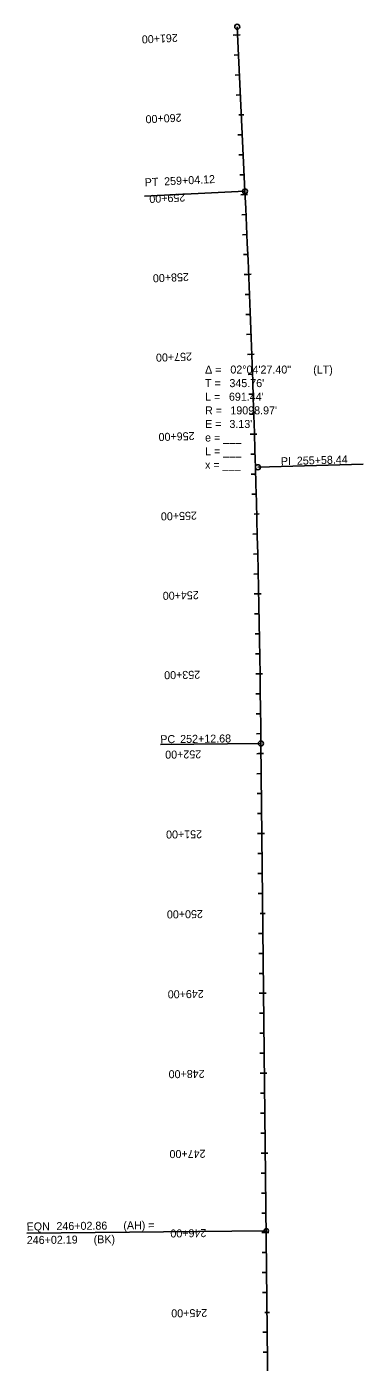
# Model space of a CAD drawing. Extents: x 23417911 to 23421158, y 6737892 to 6791804.
# Drawn here: x 23417967 to 23418389, y 6750912 to 6752584 of the extents above; entities that cross this region are included whole.
import ezdxf

# ---------------------------------------------------------------- set-up
doc = ezdxf.new("R2010")
doc.units = 0
for name, color, linetype in [('Alignment', 7, 'Continuous'), ('TextAlignment', 7, 'Continuous'), ('TextAlignmentLrg', 7, 'Continuous'), ('TextAlignmentSml', 7, 'Continuous')]:
    doc.layers.add(name, color=color, linetype=linetype)

msp = doc.modelspace()

# ---------------------------------------------------------------- linework, layer by layer
at = {"layer": 'Alignment'}
for p, q in [((23418240.7, 6752377.7), (23418231, 6752583.7)), ((23418240.7, 6752377.7), (23418231, 6752583.7)), ((23418292.6, 6748745.2), (23418260.7, 6751686.6)), ((23418292.6, 6748745.2), (23418260.7, 6751686.6))]:
    msp.add_line(p, q, dxfattribs=at)
msp.add_arc((23399162.8, 6751479.5), 19099, 0.62113, 2.69541, dxfattribs=at)
msp.add_arc((23399162.8, 6751479.5), 19099, 0.62113, 2.69541, dxfattribs=at)
at = {"layer": 'TextAlignment'}
for p, q in [((23418240.7, 6752377.7), (23418114.8, 6752371.8)), ((23418114.8, 6752371.8), (23418114.8, 6752371.8)), ((23418256.9, 6752032.3), (23418388.9, 6752036.1)), ((23418388.9, 6752036.1), (23418388.9, 6752036.1)), ((23418260.7, 6751686.6), (23418134.7, 6751685.2)), ((23418134.7, 6751685.2), (23418134.7, 6751685.2)), ((23418267.3, 6751076.8), (23417967.3, 6751073.5))]:
    msp.add_line(p, q, dxfattribs=at)
for centre, radius in [((23418231, 6752583.7), 3.12), ((23418240.7, 6752377.7), 3.12), ((23418256.9, 6752032.3), 3.12), ((23418260.7, 6751686.6), 3.12), ((23418267.3, 6751076.8), 2.67)]:
    msp.add_circle(centre, radius, dxfattribs=at)
at = {"layer": 'TextAlignmentLrg'}
for p, q in [((23418231.5, 6752573.4), (23418226, 6752573.1)), ((23418233.1, 6752473.3), (23418239.2, 6752473.6)), ((23418240.9, 6752373.6), (23418235.4, 6752373.3)), ((23418245.3, 6752273.7), (23418239.8, 6752273.4)), ((23418249.2, 6752173.7), (23418243.7, 6752173.6)), ((23418252.6, 6752073.8), (23418247.1, 6752073.6)), ((23418252.4, 6751973.8), (23418258.5, 6751973.9)), ((23418257.7, 6751873.9), (23418252.3, 6751873.8)), ((23418259.5, 6751773.9), (23418254.1, 6751773.8)), ((23418260.8, 6751673.9), (23418255.4, 6751673.8)), ((23418261.9, 6751573.9), (23418256.5, 6751573.8)), ((23418259.9, 6751473.9), (23418266.1, 6751473.9)), ((23418264.1, 6751373.9), (23418258.6, 6751373.9)), ((23418265.2, 6751273.9), (23418259.7, 6751273.9)), ((23418266.3, 6751173.9), (23418260.8, 6751173.9)), ((23418267.3, 6751074.6), (23418261.9, 6751074.5)), ((23418265.4, 6750974.6), (23418271.5, 6750974.6))]:
    msp.add_line(p, q, dxfattribs=at)
at = {"layer": 'TextAlignmentSml'}
for p, q in [((23418228.4, 6752573.2), (23418234.5, 6752573.5)), ((23418232.6, 6752548.4), (23418227.2, 6752548.1)), ((23418233.8, 6752523.4), (23418228.4, 6752523.2)), ((23418235, 6752498.4), (23418229.5, 6752498.2)), ((23418233.1, 6752473.3), (23418239.2, 6752473.6)), ((23418237.4, 6752448.5), (23418231.9, 6752448.2)), ((23418238.5, 6752423.5), (23418233.1, 6752423.3)), ((23418239.7, 6752398.5), (23418234.2, 6752398.3)), ((23418237.8, 6752373.4), (23418243.9, 6752373.7)), ((23418242, 6752348.6), (23418236.6, 6752348.4)), ((23418243.2, 6752323.6), (23418237.7, 6752323.4)), ((23418244.2, 6752298.7), (23418238.8, 6752298.4)), ((23418242.2, 6752273.5), (23418248.4, 6752273.8)), ((23418246.3, 6752248.7), (23418240.9, 6752248.5)), ((23418247.3, 6752223.7), (23418241.9, 6752223.5)), ((23418248.3, 6752198.7), (23418242.8, 6752198.5)), ((23418246.1, 6752173.6), (23418252.3, 6752173.9)), ((23418250.1, 6752148.8), (23418244.6, 6752148.6)), ((23418250.9, 6752123.8), (23418245.5, 6752123.6)), ((23418251.8, 6752098.8), (23418246.3, 6752098.6)), ((23418249.5, 6752073.7), (23418255.6, 6752073.9)), ((23418253.3, 6752048.8), (23418247.9, 6752048.7)), ((23418254.1, 6752023.8), (23418248.6, 6752023.7)), ((23418254.8, 6751998.8), (23418249.3, 6751998.7)), ((23418252.4, 6751973.8), (23418258.5, 6751973.9)), ((23418256, 6751948.9), (23418250.6, 6751948.7)), ((23418256.6, 6751923.9), (23418251.2, 6751923.7)), ((23418257.2, 6751898.9), (23418251.8, 6751898.7)), ((23418254.7, 6751873.8), (23418260.8, 6751873.9)), ((23418258.2, 6751848.9), (23418252.8, 6751848.8)), ((23418258.7, 6751823.9), (23418253.3, 6751823.8)), ((23418259.1, 6751798.9), (23418253.7, 6751798.8)), ((23418256.5, 6751773.8), (23418262.6, 6751773.9)), ((23418259.9, 6751748.9), (23418254.5, 6751748.8)), ((23418260.3, 6751723.9), (23418254.8, 6751723.8)), ((23418260.6, 6751698.9), (23418255.1, 6751698.8)), ((23418257.8, 6751673.9), (23418263.9, 6751673.9)), ((23418261.1, 6751648.9), (23418255.6, 6751648.8)), ((23418261.4, 6751623.9), (23418255.9, 6751623.8)), ((23418261.6, 6751598.9), (23418256.2, 6751598.8)), ((23418258.9, 6751573.9), (23418265, 6751573.9)), ((23418262.2, 6751548.9), (23418256.7, 6751548.8)), ((23418262.5, 6751523.9), (23418257, 6751523.8)), ((23418262.7, 6751498.9), (23418257.3, 6751498.8)), ((23418259.9, 6751473.9), (23418266.1, 6751473.9)), ((23418263.3, 6751448.9), (23418257.8, 6751448.9)), ((23418263.5, 6751423.9), (23418258.1, 6751423.9)), ((23418263.8, 6751398.9), (23418258.4, 6751398.9)), ((23418261, 6751373.9), (23418267.1, 6751373.9)), ((23418264.4, 6751348.9), (23418258.9, 6751348.9)), ((23418264.6, 6751323.9), (23418259.2, 6751323.9)), ((23418264.9, 6751298.9), (23418259.4, 6751298.9)), ((23418262.1, 6751273.9), (23418268.2, 6751274)), ((23418265.4, 6751248.9), (23418260, 6751248.9)), ((23418265.7, 6751223.9), (23418260.2, 6751223.9)), ((23418266, 6751198.9), (23418260.5, 6751198.9)), ((23418263.2, 6751173.9), (23418269.3, 6751174)), ((23418266.5, 6751148.9), (23418261.1, 6751148.9)), ((23418266.8, 6751123.9), (23418261.3, 6751123.9)), ((23418267.1, 6751098.9), (23418261.6, 6751098.9)), ((23418264.3, 6751074.6), (23418270.4, 6751074.6)), ((23418267.6, 6751049.6), (23418262.1, 6751049.5)), ((23418267.9, 6751024.6), (23418262.4, 6751024.5)), ((23418268.1, 6750999.6), (23418262.7, 6750999.5)), ((23418265.4, 6750974.6), (23418271.5, 6750974.6)), ((23418268.7, 6750949.6), (23418263.2, 6750949.6)), ((23418269, 6750924.6), (23418263.5, 6750924.6))]:
    msp.add_line(p, q, dxfattribs=at)

# ---------------------------------------------------------------- texts
at = {"layer": 'TextAlignment'}
for s, rotation, p in [('PT', 2.6954, (23418115.4, 6752383.9)), ('259+04.12', 2.6954, (23418139.7, 6752385.1)), ('PI ', 1.6583, (23418285.8, 6752034.8)), ('255+58.44', 1.6583, (23418305.8, 6752035.4)), ('PC', 0.6211, (23418134.7, 6751686.9)), ('252+12.68', 0.6211, (23418159.6, 6751687.2)), ('EQN ', 0.6211, (23417967.3, 6751077)), ('246+02.86', 0.6211, (23418004.6, 6751077.5)), ('(AH) = ', 0.6211, (23418088.4, 6751078.4)), ('246+02.19', 0.6211, (23417967.5, 6751060)), ('(BK)', 0.6211, (23418051.2, 6751060.9))]:
    msp.add_text(s, height=10.02, rotation=rotation, dxfattribs=at).set_placement(p)
for s, p in [('Δ = ', (23418190.7, 6752149.6)), ('02°04\'27.40"', (23418222.4, 6752149.6)), (' (LT)', (23418322.4, 6752149.6)), ('T = ', (23418190.7, 6752132.6)), ("345.76'", (23418221.2, 6752132.6)), ('L = ', (23418190.7, 6752115.6)), ("691.44'", (23418220.6, 6752115.6)), ('R = ', (23418190.7, 6752098.5)), ("19098.97'", (23418222.4, 6752098.5)), ('E = ', (23418190.7, 6752081.5)), ("3.13'", (23418221.2, 6752081.5)), ('e = ___ ', (23418190.7, 6752064.5)), ('L = ___', (23418190.7, 6752047.4)), ('x = ___', (23418190.7, 6752030.4))]:
    msp.add_text(s, height=10.02, dxfattribs=at).set_placement(p)
at = {"layer": 'TextAlignmentLrg'}
for s, rotation, p in [('260+00', 182.6954, (23418161, 6752474.9)), ('255+00', 181.4831, (23418180.3, 6751976.9)), ('250+00', 180.6211, (23418187.9, 6751478.1)), ('245+00', 180.6211, (23418193.4, 6750978.8))]:
    msp.add_text(s, height=10.02, rotation=rotation, dxfattribs=at).set_placement(p)
at = {"layer": 'TextAlignmentSml'}
for s, rotation, p in [('261+00', 182.6954, (23418156.3, 6752574.8)), ('260+00', 182.6954, (23418161, 6752474.9)), ('259+00', 182.6831, (23418165.7, 6752375.1)), ('258+00', 182.3831, (23418170.2, 6752275.6)), ('257+00', 182.0831, (23418174.1, 6752176)), ('256+00', 181.7831, (23418177.4, 6752076.5)), ('255+00', 181.4831, (23418180.3, 6751976.9)), ('254+00', 181.1831, (23418182.7, 6751877.3)), ('253+00', 180.8831, (23418184.5, 6751777.7)), ('252+00', 180.6211, (23418185.8, 6751678.1)), ('251+00', 180.6211, (23418186.9, 6751578.1)), ('250+00', 180.6211, (23418187.9, 6751478.1)), ('249+00', 180.6211, (23418189, 6751378.1)), ('248+00', 180.6211, (23418190.1, 6751278.1)), ('247+00', 180.6211, (23418191.2, 6751178.1)), ('246+00', 180.6211, (23418192.3, 6751078.8)), ('245+00', 180.6211, (23418193.4, 6750978.8))]:
    msp.add_text(s, height=10.02, rotation=rotation, dxfattribs=at).set_placement(p)

doc.saveas('drawing.dxf')
